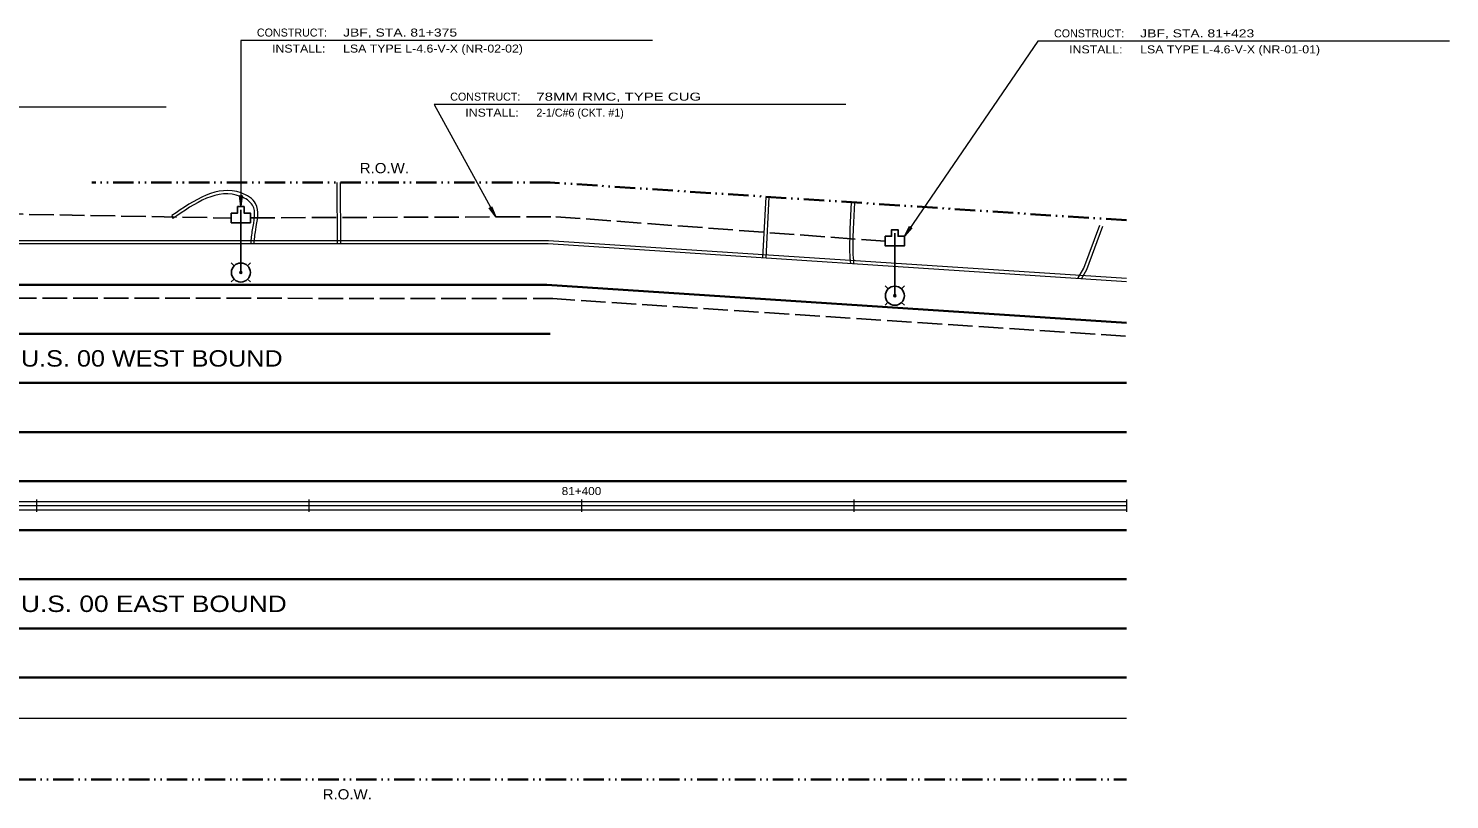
# Model space of a CAD drawing. Extents: x 168423 to 169396, y 223543 to 223937.
# Drawn here: x 168526.9 to 168631.2, y 223612.7 to 223669.3 of the extents above; entities that cross this region are included whole.
import ezdxf
from ezdxf.enums import TextEntityAlignment as Align

# ---------------------------------------------------------------- set-up
doc = ezdxf.new("R2010")
doc.units = 0
doc.header["$LTSCALE"] = 0.3
doc.header["$PDMODE"] = 32
doc.header["$PDSIZE"] = 0.15
doc.linetypes.add('DASH_DOUBLE_DOT', pattern=[9.2, 5, -1.2, 0.3, -1.2, 0.3, -1.2])
doc.linetypes.add('LONG_DASHED', pattern=[7.5, 6, -1.5])
for name, color, linetype, lineweight in [('1', 7, 'Continuous', 13), ('12', 7, 'Continuous', 13), ('32', 7, 'Continuous', 25), ('36', 7, 'Continuous', 35), ('5', 7, 'LONG_DASHED', 25), ('6', 7, 'Continuous', 25), ('8', 7, 'Continuous', 25)]:
    doc.layers.add(name, color=color, linetype=linetype, lineweight=lineweight)

msp = doc.modelspace()

# ---------------------------------------------------------------- linework, layer by layer
at = {"layer": '1', "linetype": 'DASH_DOUBLE_DOT', "lineweight": 35}
for p, q in [((168565.1597, 223657.9671), (168531.5216, 223657.9671)), ((168607.4519, 223655.1989), (168565.1597, 223657.9671)), ((168506.4362, 223614.1671), (168607.4519, 223614.1672))]:
    msp.add_line(p, q, dxfattribs=at)
at = {"layer": '1'}
for p, q in [((168549.5523, 223653.4673), (168549.524, 223657.9671)), ((168549.7823, 223653.4673), (168549.754, 223657.9671)), ((168580.9771, 223656.9318), (168580.7423, 223652.4377)), ((168581.2066, 223656.9168), (168580.9718, 223652.4227)), ((168587.1792, 223654.5521), (168587.2752, 223656.5195)), ((168587.409, 223654.5408), (168587.5048, 223656.5045)), ((168537.3783, 223655.5399), (168537.4497, 223655.3213)), ((168587.1641, 223653.9343), (168587.1792, 223654.5521)), ((168587.3941, 223653.9286), (168587.4092, 223654.5464)), ((168604.3331, 223651.6934), (168605.4986, 223654.8456)), ((168604.5421, 223651.5956), (168605.7143, 223654.7659)), ((168565.0197, 223653.6973), (168455.0122, 223653.6972)), ((168565.0122, 223653.4673), (168455.0122, 223653.4672)), ((168607.4519, 223650.6894), (168565.0122, 223653.4673)), ((168607.4519, 223650.9199), (168565.0197, 223653.6973)), ((168603.8911, 223650.9225), (168604.3331, 223651.6934)), ((168604.1466, 223650.9058), (168604.5421, 223651.5956)), ((168427.4519, 223634.5672), (168607.4519, 223634.5673)), ((168527.4519, 223634.7173), (168527.4519, 223633.8172)), ((168547.4519, 223634.7173), (168547.4518, 223633.8172)), ((168567.4518, 223634.7173), (168567.4519, 223633.8172)), ((168587.4519, 223634.7173), (168587.4519, 223633.8174)), ((168607.4519, 223634.7173), (168607.4519, 223633.8174)), ((168427.4519, 223634.2672), (168607.4519, 223634.2673)), ((168427.4519, 223633.9672), (168607.4519, 223633.9674)), ((168501.8189, 223618.6672), (168607.4519, 223618.6673))]:
    msp.add_line(p, q, dxfattribs=at)
for points in [[(168543.4261, 223653.4673), (168543.5399, 223654.493), (168543.5348, 223656.4299), (168542.473, 223657.2046), (168537.3783, 223655.5399)], [(168543.1978, 223653.495), (168543.3099, 223654.5054), (168543.3051, 223656.3128), (168542.4325, 223656.9494), (168537.4497, 223655.3213)], [(168587.2203, 223652.0137), (168587.1577, 223652.8722), (168587.1641, 223653.9343)], [(168587.449, 223652.04), (168587.3878, 223652.8799), (168587.3941, 223653.9329)]]:
    msp.add_spline(points, degree=3, dxfattribs=at)
at = {"layer": '12'}
for points in [[(168572.6619, 223668.3883), (168542.4541, 223668.3883), (168542.4542, 223656.2021)], [(168631.1654, 223668.3286), (168600.9576, 223668.3286), (168591.1522, 223654.0323)], [(168586.8495, 223663.6877), (168556.6417, 223663.6877), (168561.1553, 223655.4482)], [(168536.962, 223663.4967), (168506.7542, 223663.4967), (168510.453, 223655.931)]]:
    msp.add_lwpolyline(points, dxfattribs=at)
for points in [[(168542.5536, 223657.0154), (168542.4542, 223656.2021), (168542.3458, 223657.0154), (168542.4542, 223656.934)], [(168560.8517, 223656.2092), (168561.1553, 223655.4482), (168560.6695, 223656.1094), (168560.8037, 223656.0901)], [(168591.6942, 223654.6468), (168591.1522, 223654.0323), (168591.5228, 223654.7643), (168591.5662, 223654.6359)]]:
    msp.add_lwpolyline(points, close=True, dxfattribs=at)
at = {"layer": '32'}
for p, q in [((168542.4541, 223655.9672), (168542.4541, 223651.3672)), ((168590.4519, 223654.2672), (168590.4519, 223649.6672))]:
    msp.add_line(p, q, dxfattribs=at)
at = {"layer": '36'}
for p, q in [((168564.9157, 223650.4672), (168455.0124, 223650.4671)), ((168607.4519, 223647.683), (168564.9157, 223650.4672)), ((168427.4519, 223646.8671), (168565.1597, 223646.8672)), ((168427.4519, 223643.2671), (168607.4519, 223643.2672)), ((168427.4519, 223639.6671), (168607.4519, 223639.6672)), ((168427.4519, 223636.0671), (168607.4519, 223636.0672)), ((168427.4519, 223632.4671), (168607.4519, 223632.4673)), ((168427.4519, 223628.8671), (168607.4519, 223628.8673)), ((168427.4519, 223625.2671), (168607.4519, 223625.2673)), ((168427.4519, 223621.667), (168607.4519, 223621.6672))]:
    msp.add_line(p, q, dxfattribs=at)
at = {"layer": '5'}
for p in [(168451.4028, 223649.563), (168607.388, 223646.706)]:
    msp.add_line(p, (168565.3437, 223649.458), dxfattribs=at)
at = {"layer": '6', "linetype": 'LONG_DASHED'}
msp.add_line((168502.1771, 223656.081), (168541.7448, 223655.364), dxfattribs=at)
at = {"layer": '6'}
for points in [[(168541.7448, 223655.7323), (168542.2147, 223655.7323), (168542.2147, 223656.2021), (168542.6936, 223656.2021), (168542.6936, 223655.7323), (168543.1544, 223655.7323), (168543.1544, 223655.0184), (168541.7448, 223655.0184)], [(168589.7426, 223654.0323), (168590.2125, 223654.0323), (168590.2125, 223654.5021), (168590.6914, 223654.5021), (168590.6914, 223654.0323), (168591.1522, 223654.0323), (168591.1522, 223653.3184), (168589.7426, 223653.3184)]]:
    msp.add_lwpolyline(points, close=True, dxfattribs=at)
at = {"layer": '6', "linetype": 'LONG_DASHED'}
msp.add_lwpolyline([(168543.1544, 223655.3841), (168565.5584, 223655.4639), (168589.7426, 223653.6581)], dxfattribs=at)
at = {"layer": '8'}
for p, q in [((168541.7402, 223652.0856), (168541.9661, 223651.8597)), ((168542.933, 223651.8687), (168543.1589, 223652.0856)), ((168541.7493, 223650.676), (168541.9481, 223650.8838)), ((168542.9511, 223650.8747), (168543.1589, 223650.676)), ((168589.738, 223650.3856), (168589.9639, 223650.1597)), ((168590.9308, 223650.1687), (168591.1567, 223650.3856)), ((168589.7471, 223648.976), (168589.9459, 223649.1838)), ((168590.9489, 223649.1747), (168591.1567, 223648.976))]:
    msp.add_line(p, q, dxfattribs=at)
for centre in [(168542.4541, 223651.3672), (168590.4519, 223649.6672)]:
    msp.add_circle(centre, 0.6965, dxfattribs=at)
for p in [(168542.4541, 223651.3717), (168590.4519, 223649.6717)]:
    msp.add_point(p, dxfattribs=at)

# ---------------------------------------------------------------- texts
at = {"layer": '1'}
for s, height, width, p in [('R.O.W.', 0.7499, 1.1, (168552.983, 223658.6536)), ('ROUTE U.S. 00 WEST BOUND', 1.202, 1.15, (168532.4221, 223644.4663)), ('81+400', 0.5873, 1.1, (168567.4515, 223635.0442)), ('ROUTE U.S. 00 EAST BOUND', 1.202, 1.2, (168532.4221, 223626.4663)), ('R.O.W.', 0.7499, 1.1, (168550.2624, 223612.7172))]:
    msp.add_text(s, height=height, dxfattribs=dict(at, width=width)).set_placement(p, align=Align.CENTER)
at = {"layer": '12'}
for s, p in [('CONSTRUCT:', (168543.6288, 223668.6775)), ('CONSTRUCT:', (168602.1323, 223668.6178)), ('CONSTRUCT:', (168557.8164, 223663.9769)), ('2-1/C#6 (CKT. #1)                 ', (168564.1417, 223662.8022))]:
    msp.add_text(s, height=0.5873, dxfattribs=at).set_placement(p)
for s, width, p in [('JBF, STA. 81+375                     ', 1.3, (168549.9541, 223668.6775)), ('JBF, STA. 81+423               ', 1.3, (168608.4576, 223668.6178)), ('LSA TYPE L-4.6-V-X (NR-02-02)          ', 1.15, (168549.9541, 223667.5028)), ('LSA TYPE L-4.6-V-X (NR-01-01)          ', 1.15, (168608.4576, 223667.4431)), ('78MM RMC, TYPE CUG                   ', 1.4, (168564.1417, 223663.9769))]:
    msp.add_text(s, height=0.5873, dxfattribs=dict(at, width=width)).set_placement(p)
at = {"layer": '12', "width": 1.15}
for p in [(168548.656, 223667.5028), (168607.1595, 223667.4431), (168562.8436, 223662.8022)]:
    msp.add_text('INSTALL:', height=0.5873, dxfattribs=at).set_placement(p, align=Align.RIGHT)

doc.saveas('drawing.dxf')
